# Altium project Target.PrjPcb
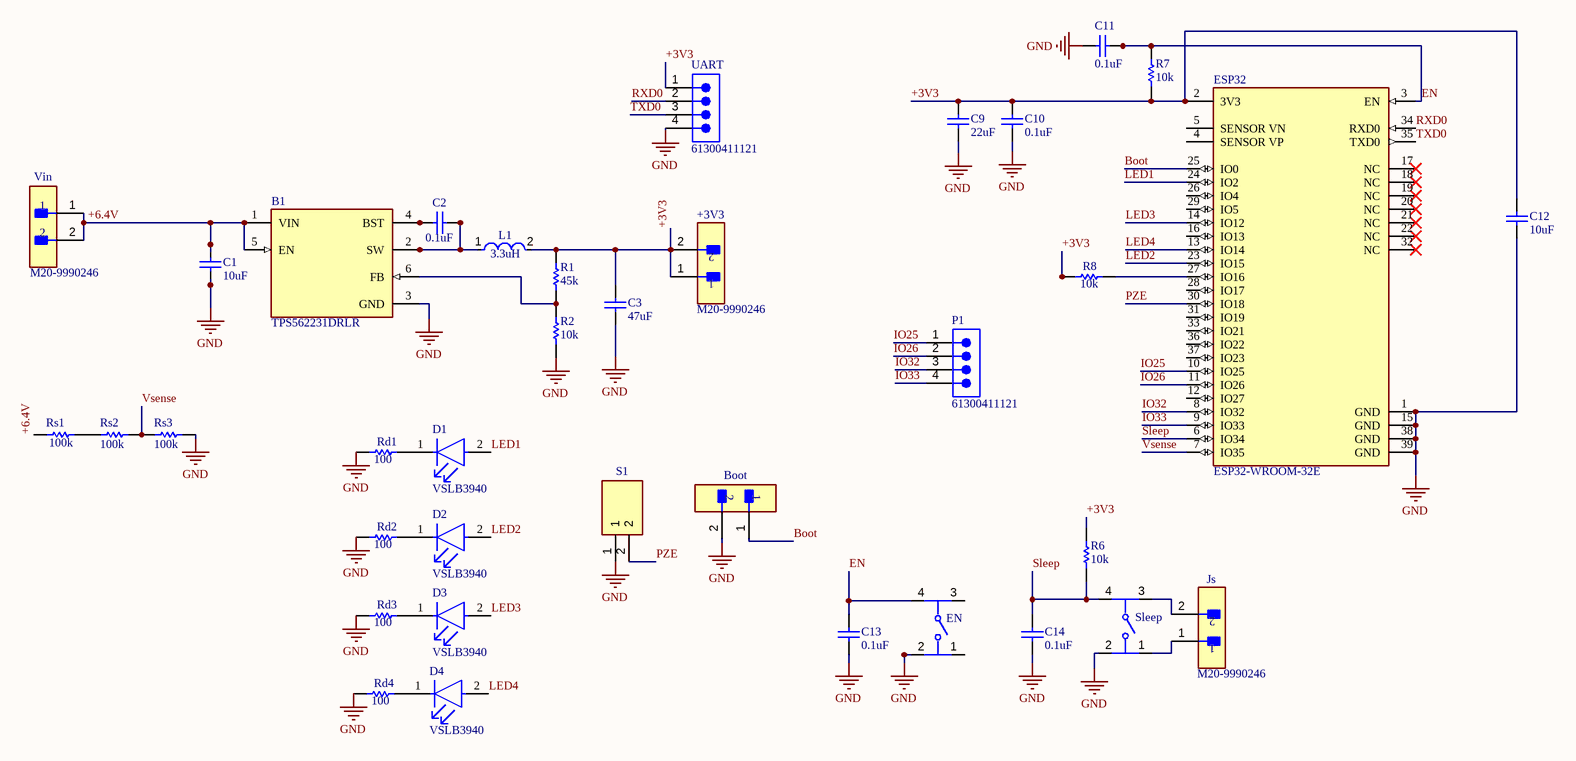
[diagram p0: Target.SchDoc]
1 sheet, 37 parts. Net scope: global (net labels, ports and power ports of the same name join across sheets).
Board file: Target.PcbDoc

## Sheet Target.SchDoc
size 350 x 199 mm; Organization: ORGANIZATION; Address1: ADDRESS 1; Address2: ADDRESS 2; Address3: ADDRESS 3; Address4: ADDRESS 4; Revision: -; SheetNumber: 1; SheetTotal: 1; ENG_APP_DATE: --/--/--; DSN_APP_DATE: --/--/--; CHK_APP_DATE: --/--/--

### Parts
+3V3  M20-9990246  [FP-M20-9990246-MFG]
B1  TPS562231DRLR  [FP-DRL0006A-MFG]
Boot  M20-9990246  [FP-M20-9990246-MFG]  (value not drawn)
C1  10uF  [CAPC2013X88X50LL20T25]
C2  0.1uF  [CAPC2013X88X50LL20T25]
C3  47uF  [CAPC2013X88X50LL20T25]
C9  22uF  [CAPC2013X88X50LL20T25]
C10  0.1uF  [CAPC2013X88X50LL20T25]
C11  0.1uF  [CAPC2013X88X50LL20T25]
C12  10uF  [CAPC2013X88X50LL20T25]
C13  0.1uF  [CAPC2013X88X50LL20T25]
C14  0.1uF  [CAPC2013X88X50LL20T25]
D1  VSLB3940  [FP-VSLB3940-MFG]
D2  VSLB3940  [FP-VSLB3940-MFG]
D3  VSLB3940  [FP-VSLB3940-MFG]
D4  VSLB3940  [FP-VSLB3940-MFG]
EN  PTS647SK38SMTR2LFS  [FP-PTS647SK38SMTR2LFS-MFG]  (value not drawn)
ESP32  ESP32-WROOM-32E  [FP-ESP32-WROOM-32E_M113EH-MFG]
Js  M20-9990246  [FP-M20-9990246-MFG]
L1  3.3uH  [FP-NR4012-MFG]
P1  61300411121  [61300411121]
R1  45k  [RESC2013X60X35ML10T20]
R2  10k  [RESC2013X60X35ML10T20]
R6  10k  [RESC2013X60X35ML10T20]
R7  10k  [RESC2013X60X35ML10T20]
R8  10k  [RESC2013X60X35ML10T20]
Rd1  100  [RESC2013X60X35ML10T20]
Rd2  100  [RESC2013X60X35ML10T20]
Rd3  100  [RESC2013X60X35ML10T20]
Rd4  100  [RESC2013X60X35ML10T20]
Rs1  100k  [RESC2013X60X35ML10T20]
Rs2  100k  [RESC2013X60X35ML10T20]
Rs3  100k  [RESC2013X60X35ML10T20]
S1  EBAFA-02-D  [EBAFA02D]  (value not drawn)
Sleep  PTS647SK38SMTR2LFS  [FP-PTS647SK38SMTR2LFS-MFG]  (value not drawn)
UART  61300411121  [61300411121]
Vin  M20-9990246  [FP-M20-9990246-MFG]

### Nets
GND: B1.3(GND) Boot.2 C1.2 C3.2 C9.2 C10.2 C11.1 C12.2 C13.2 C14.2 EN.2 ESP32.1(GND) ESP32.15(GND) ESP32.38(GND) ESP32.39(GND) R2.1 Rd1.2 Rd2.2 Rd3.2 Rd4.2 Rs3.1 S1.1 Sleep.2 UART.4
+3V3: +3V3.1 +3V3.2 C3.1 C9.1 C10.1 C12.1 ESP32.2(3V3) L1.2 R1.2 R6.2 R7.1 R8.2 UART.1
+6.4V: B1.1(VIN) B1.5(EN) C1.1 Rs1.2 Vin.1 Vin.2
Boot: Boot.1 ESP32.25(IO0)
EN: C11.2 C13.1 EN.4 ESP32.3(EN) R7.2
IO25: ESP32.10(IO25) P1.1
IO26: ESP32.11(IO26) P1.2
IO32: ESP32.8(IO32) P1.3
IO33: ESP32.9(IO33) P1.4
LED1: D1.2(A) ESP32.24(IO2)
LED2: D2.2(A) ESP32.23(IO15)
LED3: D3.2(A) ESP32.14(IO12)
LED4: D4.2(A) ESP32.13(IO14)
PZE: ESP32.30(IO18) S1.2
RXD0: ESP32.34(RXD0) UART.2
Sleep: C14.1 ESP32.6(IO34) R6.1 Sleep.4
TXD0: ESP32.35(TXD0) UART.3
Vsense: ESP32.7(IO35) Rs2.1 Rs3.2
NetB1_2: B1.2(SW) C2.1 L1.1
NetB1_4: B1.4(BST) C2.2
NetB1_6: B1.6(FB) R1.1 R2.2
NetD1_1: D1.1(C) Rd1.1
NetD2_1: D2.1(C) Rd2.1
NetD3_1: D3.1(C) Rd3.1
NetD4_1: D4.1(C) Rd4.1
NetESP32_27: ESP32.27(IO16) R8.1
NetJs_1: Js.1 Sleep.1
NetJs_2: Js.2 Sleep.3
NetRs1_1: Rs1.1 Rs2.2

Not connected (* = marked no-connect by the designer): EN 1 3; ESP32 4(SENSOR_VP) 5(SENSOR_VN) 12(IO27) 16(IO13) 17(NC)* 18(NC)* 19(NC)* 20(NC)* 21(NC)* 22(NC)* 26(IO4) 28(IO17) 29(IO5) 31(IO19) 32(NC)* 33(IO21) 36(IO22) 37(IO23)

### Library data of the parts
+3V3 Boot Js Vin = CMP-15831-000009-1: CONN HEADER VERT 2POS 2.54MM; Manufacturer: Harwin; Conn Gender: Male; Conn Orientation: Vertical; Number Of Contacts: 2; Current Rating: 3A
B1 = CMP-04918-000372-1: POWER MANAGEMENT
C1-C3 C9-C14 = CMP-2007-00266-1: Manufacturer: Kemet; Part Number: C0805C103K5RACTU
D1-D4 = CMP-00030-18785862-1: VSLB3940 940 nm 100 mA ±22° Through Hole High Speed Infrared Emitting Diode - T-1; Power Rating: 160mW; Rise Time: 15ns; Peak Wavelength: 940nm; Lens Style: Circular, Diffused, Round; Reverse Voltage: 5V; Viewing Angle: 44°; Forward Current: 100mA; Number of Elements: 1; Forward Voltage: 1.35V
EN Sleep = CMP-10040-000033-1: TACT 4.5 X 4.5, 3.8 MM H, 2.5N,; Switch Function: Off-Mom; Switch Travel: 0.25mm; Actuator Type: Standard; Illumination Type: Non-Illuminated; Mechanical Life: 100000Cycles; Ratings: IP40; Operating Force: 250gf; Throw Configuration: SPST
ESP32 = CMP-194065-000012-1: RX TXRX MOD WIFI TRACE ANT SMD
L1 = CMP-14484-001001-1: SMD Power Inductors 3.3uH ±20% 1.4A 84mΩ; Self Resonant Frequency: 60MHz; Max DC Current: 1.7A; DC Resistance (DCR): 84mR; Test Frequency: 100kHz; Core Material: Ferrite; Shielding: Shielded
P1 UART = CMP-1502-01064-3: NexarPartId: 32855522; Operating Supply Voltage: 250V; Pitch: 2.54mm; Contact Resistance: 20mΩ; Number of Positions: 4; Current Rating: 3A; Connector Type: Male Pin; Gender: Male
R1 R2 R6-R8 Rd1-Rd4 Rs1-Rs3 = CMP-2100-03671-1: Chip Resistor, 1 KOhm, +/- 1%, 125 mW, -55 to 155 degC, 0805 (2012 Metric), RoHS, Tape and Reel; Manufacturer: Yageo; Temperature Coefficient: 100ppm/degreesC; Voltage Rating (DC): 150V; Max Power Dissipation: 125mW; Resistance: 1KOhm
S1 = EBAFA-02-D: Connector; Manufacturer_Name: Adam Tech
